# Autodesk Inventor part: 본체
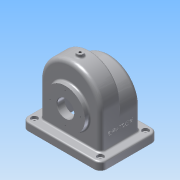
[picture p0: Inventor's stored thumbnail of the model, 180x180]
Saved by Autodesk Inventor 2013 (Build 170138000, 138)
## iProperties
Created: 2017-11
Part Number: 본체
Material: 알루미늄 6061
Document SubType Name: Modeling
Designer: Administrator
Density: 2.71 g/cm^3
Mass: 1079.71 g
Surface Area: 1182.06 cm^2
Volume: 398.416 cm^3
Author: Administrator
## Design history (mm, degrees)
sketch "스케치1"
  geometry: L1 (-58, 80)-(-58, 0); L2 (58, 80)-(58, 0); L3 (-58, 0)-(58, 0); A1 r 58 centre (0, 80) between (58, 80) and (-58, 80); 2 further points
  constraints: 6 end point, 2 point on circle, 2 tangent, 1 centre point, 1 coincident, 1 parallel, 1 perpendicular, 1 vertical, 1 vertical alignment
  dimensions: "d0" = 116 diameter of A1; "d2" = 80 distance of point (0, 0) A1.centre; "d3" = 80 distance from line of L3 A1.centre
extrude "돌출1" new body sketch "스케치1" stored distance "d4" = 38; taper "d5" = 0 deg
sketch "스케치2"
  geometry: L1 (-58, 80)-(-58, 0) reference; L2 (-58, 0)-(58, 0) reference; L3 (58, 0)-(58, 80) reference; L4 (-58, 57)-(-58, 1.222); L5 (58, 57)-(58, 0); L6 (58, 0)-(-58, 0); A1 r 58 centre (0, 57) between (10.724, 0) and (-10.724, 0); 3 further points
  constraints: 6 end point, 6 point on line, 4 point on circle, 2 collinear, 1 centre point, 1 midpoint, 1 vertical alignment
  dimensions: "d6" = 116 diameter of A1; "d7" = 57 distance of point (0, 0) A1.centre
extrude "돌출2" join sketch "스케치2" distance "d8" = 38; taper "d9" = 0 deg
feature "쉘1" dims "d10" = 5
fillet "모깎기1" dims "d11" = 3
sketch "스케치6"
  geometry: L1 (116, 0)-(116, -76) reference; L2 (0, 0)-(116, 0) reference; L3 (0, 0)-(0, -76) reference; L4 (116, -76)-(0, -76) reference; L5 (-17, 17)-(133, 17); L6 (133, 17)-(133, -93); L7 (133, -93)-(-17, -93); L8 (-17, -93)-(-17, 17); L9 (-17, 17)-(133, -93); L10 (133, 17)-(-17, -93); 6 further points
  constraints: 12 end point, 6 midpoint, 2 parallel, 1 horizontal, 1 horizontal alignment, 1 perpendicular, 1 vertical alignment
  dimensions: "d20" = 150 distance of L6.end L7.end; "d21" = 110 distance of L5.end L6.end
extrude "돌출4" join sketch "스케치6" distance "d22" = 15; taper "d23" = 0 deg
fillet "모깎기4" dims "d24" = 8
fillet "모깎기5" dims "d25" = 3, "d26" = 12
sketch "스케치7"
  geometry: A1 r 12 centre (121, 81) between (133, 81) and (121, 93) reference; A2 r 12 centre (-5, 81) between (-5, 93) and (-17, 81) reference; A3 r 12 centre (-5, -5) between (-17, -5) and (-5, -17) reference; A4 r 12 centre (121, -5) between (121, -17) and (133, -5) reference; 5 further points
  constraints: 4 coincident
hole "구멍1" sketch "스케치7" at (-5, 81), (-5, -5), (121, -5), (121, 81) diameter "d27" = 5; stored, may be unused: countersink angle "d31" = 90 deg, drill point angle "d33" = 0 deg; dims "d28" = 6, "d29" = 12, "d30" = 5, "d32" = 8
fillet "모깎기6" dims "d34" = 3
sketch "스케치8"
  geometry: L1 (-63, 0)-(63, 0) reference; C1 r 37.5 at (0, 65); A1 r 50 centre (0, 80) between (50, 80) and (-50, 80) reference; 1 further point
  constraints: 1 centre point, 1 vertical alignment
  dimensions: "d35" = 75 diameter of C1; "d36" = 65 distance from line of L1 C1.centre
extrude "돌출5" join sketch "스케치8" distance "d37" = 9; taper "d38" = 0 deg
sketch "스케치9"
  geometry: C1 r 37.5 at (0, 0) reference; C2 r 16 at (0, 0); 1 further point
  constraints: 1 centre point, 1 coincident
  dimensions: "d39" = 32 diameter of C2
extrude "돌출6" cut sketch "스케치9" stored distance "d40" = 9; taper "d41" = 0 deg
sketch "스케치10"
  geometry: C1 r 16 at (0, 0) reference; 2 further points
  constraints: 1 vertical alignment
  dimensions: "d42" = 29 distance of C1.centre point (0, 29)
hole "구멍2" sketch "스케치10" at (0, 29) diameter "d43" = 2.459; stored, may be unused: countersink angle "d47" = 90 deg, drill point angle "d49" = 118 deg; dims "d44" = 6, "d45" = 12, "d46" = 5, "d48" = 8
fillet "모깎기7" dims "d53" = 3
sketch "스케치11"
  geometry: L1 (-63, 0)-(63, 0) reference; C1 r 31 at (0, 65); A1 r 50 centre (0, 57) between (50, 57) and (-50, 57) reference; 1 further point
  constraints: 1 centre point, 1 vertical alignment
  dimensions: "d54" = 62 diameter of C1; "d55" = 65 distance from line of L1 C1.centre
extrude "돌출7" join sketch "스케치11" distance "d56" = 10; taper "d57" = 0 deg
sketch "스케치12"
  geometry: C1 r 31 at (0, 0) reference; C2 r 16 at (0, 0); 1 further point
  constraints: 1 centre point, 1 coincident
  dimensions: "d58" = 32 diameter of C2
extrude "돌출8" cut sketch "스케치12" stored distance "d59" = 10; taper "d60" = 0 deg
sketch "스케치13"
  geometry: C1 r 16 at (0, 0) reference; 2 further points
  constraints: 1 vertical alignment
  dimensions: "d61" = 26 distance of C1.centre point (0, 26)
hole "구멍3" sketch "스케치13" at (0, 26) diameter "d62" = 2.459; stored, may be unused: countersink angle "d66" = 90 deg, drill point angle "d68" = 118 deg; dims "d63" = 6, "d64" = 12, "d65" = 5, "d67" = 8
node "작업 평면1"
sketch "스케치14"
  geometry: L1 (-25.5, -8)-(-100.5, -8) reference; C1 r 6 at (-63, -36); 1 further point
  constraints: 1 centre point, 1 coincident
  dimensions: "d73" = 12 diameter of C1; "d74" = 28 distance from line of C1.centre L1
extrude "돌출9" join sketch "스케치14" stored distance "d75" = 10; taper "d76" = 0 deg
hole "구멍4" diameter "d79" = 4.459; stored, may be unused: countersink angle "d83" = 90 deg, drill point angle "d85" = 118 deg; dims "d77" = 10, "d78" = 10, "d80" = 6, "d81" = 12, "d82" = 5, "d84" = 8
fillet "모깎기8" dims "d86" = 3
chamfer "모따기1" distance "d87" = 1; stored, may be unused: second distance "d88" = 2, angle "d89" = 45 deg
sketch "스케치15"
  geometry: L1 (-35, 23)-(-35, -39) reference; L2 (-40, -57)-(46, -57) reference; 2 further points
  constraints: 1 other
  dimensions: "d90" = 38 distance from line of L1 point (3, -17); "d91" = 40 distance from line of L2 point (3, -17)
feature "엠보싱1" sketch "스케치15" dims "d0" = 116, "d2" = 80, "d3" = 80, "d92" = 0.5, "d93" = 0
fillet "모깎기10" dims "d95" = 3
node "솔리드1"
pattern_circular "원형 패턴1" dims angle "d51" = 360 deg
pattern_circular "원형 패턴2" dims angle "d70" = 360 deg
other parameters: "d72" = -144
